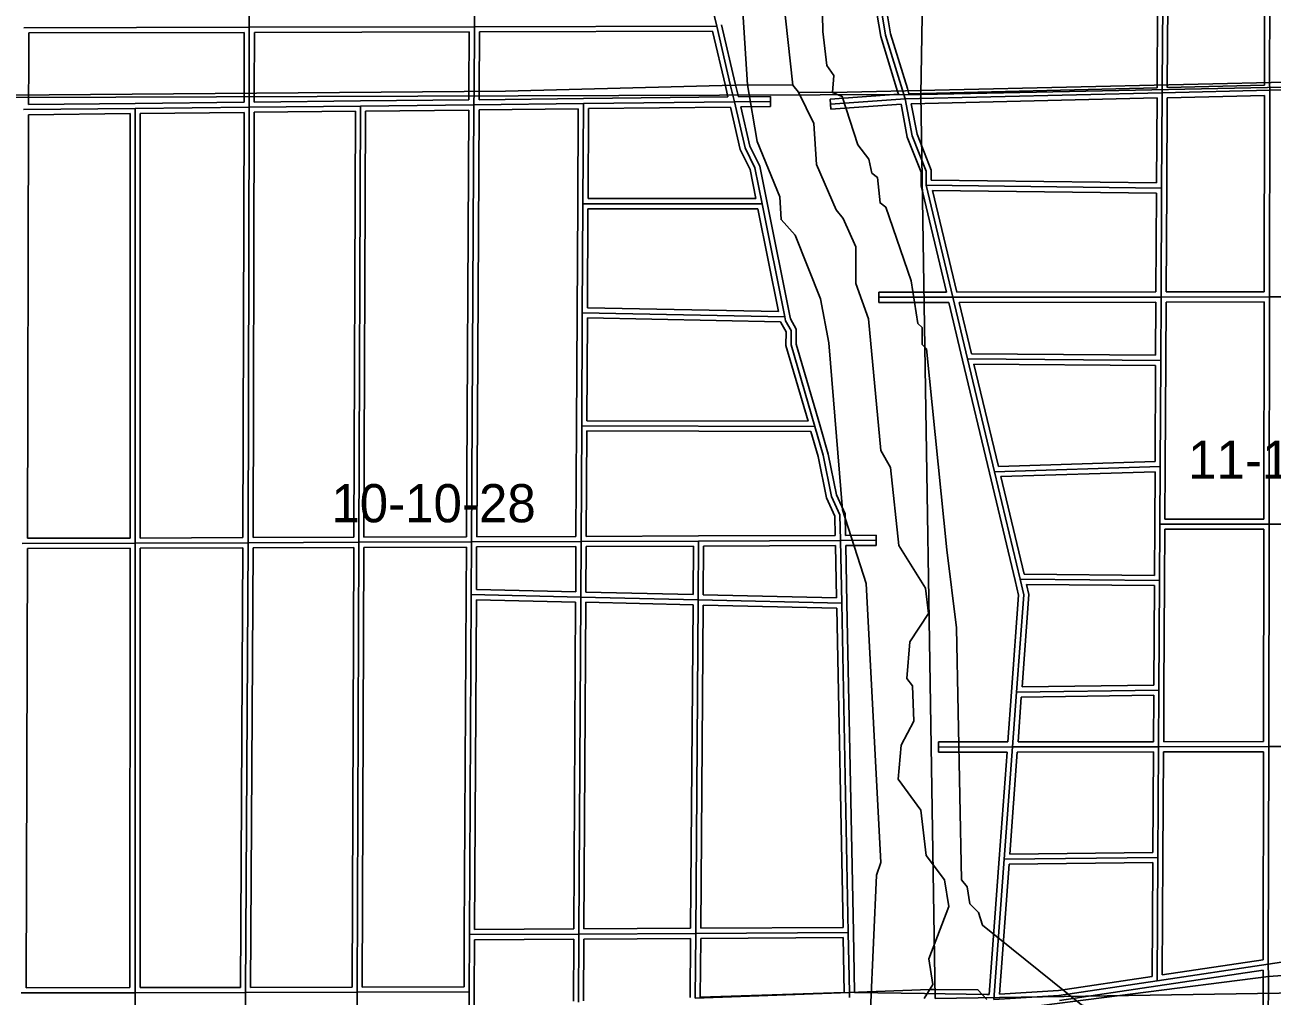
# Model space of a CAD drawing. Extents: x 418523 to 616617, y 1878279 to 2196743.
# Drawn here: x 505579 to 512924, y 1928489 to 1934208 of the extents above; entities that cross this region are included whole.
import ezdxf

# ---------------------------------------------------------------- set-up
doc = ezdxf.new("R2010")
doc.units = 0
for name, color, linetype in [('Level 1', 7, 'Continuous'), ('Level 2', 7, 'Continuous'), ('Level 31', 7, 'Continuous'), ('Level 32', 7, 'Continuous'), ('Level 5', 7, 'Continuous'), ('Level 7', 7, 'Continuous')]:
    doc.layers.add(name, color=color, linetype=linetype)

msp = doc.modelspace()

# ---------------------------------------------------------------- linework, layer by layer
at = {"layer": 'Level 1'}
for p, q in [((510939.835, 1939212.011), (510855.55, 1933798.987)), ((510855.55, 1933798.987), (516178.375, 1933906.316)), ((505521.617, 1933779.822), (510855.55, 1933798.987)), ((510855.55, 1933798.987), (510940.083, 1928474.48)), ((516240.655, 1928555.995), (510940.083, 1928474.48))]:
    msp.add_line(p, q, dxfattribs=at)
at = {"layer": 'Level 31'}
for p, q in [((506901.485, 1934859.173), (506900.067, 1934194.053)), ((508229.261, 1934859.278), (508225.655, 1934197.077)), ((509652.895, 1934200.835), (509498.59, 1934859.664)), ((512910.38, 1934429.871), (512909.801, 1933871.301)), ((512279.751, 1934325.775), (512276.974, 1933857.399)), ((505571.62, 1934191.089), (506900.067, 1934194.053)), ((506900.067, 1934194.053), (506899.148, 1933809.31)), ((506900.067, 1934194.053), (508225.655, 1934197.077)), ((508225.655, 1934197.077), (508223.83, 1933820.701)), ((508225.655, 1934197.077), (509652.895, 1934200.835)), ((509733.165, 1933856.136), (509652.895, 1934200.835)), ((509757.221, 1933754.217), (509733.165, 1933856.136)), ((512276.974, 1933857.399), (512276.782, 1933808.306)), ((512909.801, 1933871.301), (512909.934, 1933823.661)), ((506899.148, 1933809.31), (506899.115, 1933722.76)), ((508223.83, 1933820.701), (508223.495, 1933737.062)), ((510763.317, 1933772.057), (510747.321, 1933824.122)), ((510763.317, 1933772.057), (512276.782, 1933808.306)), ((512276.782, 1933808.306), (512273.642, 1933246.836)), ((512276.782, 1933808.306), (512909.934, 1933823.661)), ((512909.934, 1933823.661), (512908.071, 1932606.155)), ((512909.934, 1933823.661), (513574.537, 1933839.997)), ((505570.289, 1933708.887), (506227.872, 1933715.663)), ((506227.872, 1933715.663), (506227.648, 1931155.896)), ((506227.872, 1933715.663), (506899.115, 1933722.76)), ((506899.115, 1933722.76), (506892.566, 1931158.291)), ((506899.115, 1933722.76), (507555.111, 1933729.931)), ((507555.111, 1933729.931), (507545.411, 1931160.747)), ((507555.111, 1933729.931), (508223.495, 1933737.062)), ((508223.495, 1933737.062), (508209.375, 1931163.17)), ((508223.495, 1933737.062), (508868.055, 1933744.301)), ((508868.055, 1933744.301), (508865.069, 1933154.829)), ((508868.055, 1933744.301), (509757.221, 1933754.217)), ((509757.221, 1933754.217), (509969.745, 1933756.647)), ((510763.317, 1933772.057), (510323.875, 1933741.426)), ((510886.474, 1933263.183), (512273.642, 1933246.836)), ((511043.668, 1932603.986), (510886.474, 1933263.183)), ((512273.642, 1933246.836), (512270.19, 1932605.364)), ((508865.069, 1933154.829), (508861.555, 1932512.628)), ((508865.069, 1933154.829), (509920.667, 1933154.992)), ((510053.675, 1932488.978), (509920.667, 1933154.992)), ((511043.668, 1932603.986), (510607.509, 1932603.886)), ((512270.19, 1932605.364), (511043.668, 1932603.986)), ((511130.237, 1932241.082), (511043.668, 1932603.986)), ((512270.19, 1932605.364), (512268.1, 1932231.899)), ((512908.071, 1932606.155), (512270.19, 1932605.364)), ((512908.071, 1932606.155), (512906.058, 1931267.551)), ((513575.179, 1932607.206), (512908.071, 1932606.155)), ((508861.555, 1932512.628), (508857.949, 1931847.155)), ((508861.555, 1932512.628), (510053.675, 1932488.978)), ((511130.237, 1932241.082), (512268.1, 1932231.899)), ((511288.69, 1931576.427), (511130.237, 1932241.082)), ((512268.1, 1932231.899), (512264.714, 1931607.155)), ((508857.949, 1931847.155), (508853.96, 1931165.681)), ((508857.949, 1931847.155), (510230.927, 1931843.517)), ((511288.69, 1931576.427), (512264.714, 1931607.155)), ((511439.648, 1930943.076), (511288.69, 1931576.427)), ((512264.714, 1931607.155), (512263.075, 1931267.508)), ((512263.075, 1931267.508), (512261.147, 1930935.863)), ((512263.075, 1931267.508), (512906.058, 1931267.551)), ((512906.058, 1931267.551), (512904.156, 1929957.678)), ((512906.058, 1931267.551), (513576.045, 1931267.866)), ((505563.369, 1931154.238), (506227.648, 1931155.896)), ((506227.648, 1931155.896), (506227.388, 1928508.127)), ((506227.648, 1931155.896), (506892.566, 1931158.291)), ((506892.566, 1931158.291), (506877.735, 1928509.491)), ((506892.566, 1931158.291), (507545.411, 1931160.747)), ((507545.411, 1931160.747), (507535.706, 1928510.836)), ((507545.411, 1931160.747), (508209.375, 1931163.17)), ((508209.375, 1931163.17), (508207.817, 1930853.343)), ((508209.375, 1931163.17), (508853.96, 1931165.681)), ((508853.96, 1931165.681), (508852.336, 1930838.036)), ((508853.96, 1931165.681), (509546.197, 1931168.016)), ((509546.197, 1931168.016), (509543.87, 1930821.826)), ((509546.197, 1931168.016), (510382.348, 1931171.612)), ((510382.348, 1931171.612), (510592.021, 1931172.603)), ((510389.785, 1930802.111), (510382.348, 1931171.612)), ((511439.648, 1930943.076), (512261.147, 1930935.863)), ((512261.147, 1930935.863), (512257.365, 1930290.756)), ((508207.817, 1930853.343), (508196.62, 1928850.378)), ((508207.817, 1930853.343), (508852.336, 1930838.036)), ((508852.336, 1930838.036), (508841.25, 1928853.982)), ((508852.336, 1930838.036), (509543.87, 1930821.826)), ((509543.87, 1930821.826), (509529.406, 1928857.788)), ((509543.87, 1930821.826), (510389.785, 1930802.111)), ((510427.885, 1928863.321), (510389.785, 1930802.111)), ((511395.433, 1929955.565), (511419.255, 1930278.761)), ((511419.255, 1930278.761), (512257.365, 1930290.756)), ((512257.365, 1930290.756), (512255.427, 1929956.566)), ((512904.156, 1929957.678), (512255.427, 1929956.566)), ((512904.156, 1929957.678), (512902.05, 1928676.535)), ((513576.712, 1929958.71), (512904.156, 1929957.678)), ((511395.433, 1929955.565), (510959.559, 1929955.096)), ((511346.778, 1929294.633), (511395.433, 1929955.565)), ((512255.427, 1929956.566), (511395.433, 1929955.565)), ((512255.427, 1929956.566), (512251.62, 1929305.276)), ((511346.778, 1929294.633), (512251.62, 1929305.276)), ((512251.62, 1929305.276), (512247.199, 1928577.986)), ((511285.399, 1928467.926), (511346.778, 1929294.633)), ((508841.25, 1928853.982), (509529.406, 1928857.788)), ((509529.406, 1928857.788), (509526.306, 1928477.054)), ((509529.406, 1928857.788), (510427.885, 1928863.321)), ((510434.752, 1928509.821), (510427.885, 1928863.321)), ((508196.62, 1928850.378), (508194.951, 1928512.914)), ((508196.62, 1928850.378), (508841.25, 1928853.982)), ((508841.25, 1928853.982), (508838.696, 1928452.518)), ((512247.199, 1928577.986), (512902.05, 1928676.535)), ((512902.05, 1928676.535), (512902.086, 1928604.167)), ((511668.96, 1928491.515), (512247.199, 1928577.986)), ((512902.086, 1928604.167), (512901.062, 1927929.958)), ((505556.391, 1928506.859), (506227.388, 1928508.127)), ((506227.388, 1928508.127), (506877.735, 1928509.491)), ((506227.388, 1928508.127), (506227.392, 1928430.669)), ((506877.735, 1928509.491), (506877.416, 1928430.579)), ((506877.735, 1928509.491), (507535.706, 1928510.836)), ((507535.706, 1928510.836), (507535.385, 1928430.833)), ((507535.706, 1928510.836), (508194.951, 1928512.914)), ((508194.951, 1928512.914), (508194.305, 1928430.731)), ((510435.269, 1928479.636), (510434.752, 1928509.821)), ((511285.399, 1928467.926), (511668.96, 1928491.515))]:
    msp.add_line(p, q, dxfattribs=at)
for points in [[(510747.321, 1933824.122), (510648.215, 1934147.438), (510615.295, 1934338.123)], [(509920.667, 1933154.992), (509878.303, 1933366.808), (509820.317, 1933483.771), (509757.221, 1933754.217)], [(510886.474, 1933263.183), (510886.8, 1933346.458), (510804.395, 1933555.156), (510763.317, 1933772.057)], [(510230.927, 1931843.517), (510091.144, 1932324.094), (510091.473, 1932407.37), (510058.349, 1932465.686), (510053.675, 1932488.978)], [(510382.348, 1931171.612), (510379.131, 1931322.541), (510329.366, 1931431.108), (510280.447, 1931673.131), (510230.927, 1931843.517)], [(511419.255, 1930278.761), (511461.21, 1930851.714), (511439.648, 1930943.076)], [(512902.05, 1928676.535), (513187.194, 1928719.431), (513576.794, 1928744.834)]]:
    msp.add_lwpolyline(points, dxfattribs=at)
at = {"layer": 'Level 32'}
for p, q in [((512880.38, 1934429.901), (512879.801, 1933871.331)), ((512249.575, 1934295.997), (512246.975, 1933857.576)), ((512309.752, 1934325.596), (512306.975, 1933857.22)), ((505601.534, 1934161.154), (505600.835, 1933920.445)), ((505601.534, 1934161.155), (506869.995, 1934163.985)), ((506869.995, 1934163.985), (506869.149, 1933809.381)), ((506929.996, 1934164.12), (506929.149, 1933809.238)), ((506929.997, 1934164.121), (508195.51, 1934167.007)), ((508195.51, 1934167.007), (508193.83, 1933820.846)), ((508255.512, 1934167.154), (508253.831, 1933820.555)), ((508255.512, 1934167.155), (509629.094, 1934170.771)), ((509703.946, 1933849.331), (509629.094, 1934170.771)), ((509762.385, 1933862.94), (509682.115, 1934207.639)), ((505600.835, 1933920.41), (505600.336, 1933798.224)), ((509780.902, 1933784.49), (509762.365, 1933863.027)), ((512246.975, 1933857.516), (512246.897, 1933837.6)), ((512306.975, 1933857.281), (512306.904, 1933839.046)), ((512306.904, 1933839.046), (512879.853, 1933852.941)), ((512879.801, 1933871.217), (512879.853, 1933852.941)), ((505600.336, 1933798.331), (505600.306, 1933739.198)), ((506869.149, 1933809.321), (506869.128, 1933752.444)), ((506929.149, 1933809.298), (506929.128, 1933753.089)), ((508193.83, 1933820.821), (508193.615, 1933766.744)), ((508253.831, 1933820.581), (508253.619, 1933767.402)), ((508867.721, 1933774.299), (509719.415, 1933783.797)), ((509719.415, 1933783.797), (509703.968, 1933849.243)), ((509780.901, 1933784.49), (509969.402, 1933786.646)), ((509969.402, 1933786.646), (509970.089, 1933726.648)), ((510723.546, 1933799.357), (510321.789, 1933771.354)), ((510723.546, 1933799.357), (510718.644, 1933815.311)), ((510785.32, 1933802.593), (510775.999, 1933832.933)), ((510785.32, 1933802.592), (512246.897, 1933837.6)), ((510799.372, 1933742.911), (512246.61, 1933777.574)), ((512246.61, 1933777.573), (512243.812, 1933277.189)), ((512306.62, 1933779.021), (512303.643, 1933246.668)), ((512306.621, 1933779.02), (512879.887, 1933792.921)), ((512879.887, 1933792.921), (512878.118, 1932636.117)), ((505600.306, 1933739.198), (506227.564, 1933745.662)), ((506227.555, 1933745.661), (506869.127, 1933752.444)), ((506929.128, 1933753.089), (507554.783, 1933759.928)), ((507554.791, 1933759.928), (508193.615, 1933766.744)), ((507585, 1933700.246), (508193.329, 1933706.738)), ((508193.329, 1933706.737), (508179.54, 1931193.061)), ((508253.335, 1933707.394), (508239.543, 1931193.288)), ((508253.334, 1933707.395), (508837.9, 1933713.959)), ((508253.619, 1933767.401), (508867.719, 1933774.299)), ((508837.9, 1933713.959), (508835.069, 1933154.981)), ((508897.906, 1933714.63), (508895.222, 1933184.833)), ((508897.906, 1933714.631), (509733.477, 1933723.949)), ((509794.928, 1933724.645), (509970.089, 1933726.648)), ((510325.96, 1933711.498), (510321.789, 1933771.354)), ((510738.803, 1933740.274), (510325.96, 1933711.498)), ((505600.21, 1933679.192), (505593.451, 1931184.312)), ((505600.21, 1933679.192), (506197.87, 1933685.351)), ((506197.87, 1933685.351), (506197.65, 1931185.821)), ((506257.871, 1933685.977), (506257.651, 1931186.005)), ((506257.872, 1933685.978), (506869.039, 1933692.439)), ((506869.039, 1933692.439), (506862.643, 1931188.183)), ((506929.041, 1933693.084), (506922.645, 1931188.405)), ((506929.042, 1933693.084), (507524.997, 1933699.598)), ((507524.997, 1933699.597), (507515.525, 1931190.635)), ((507585, 1933700.246), (507575.526, 1931190.857)), ((510916.591, 1933292.83), (512243.812, 1933277.19)), ((511005.675, 1932633.977), (510856.46, 1933259.713)), ((510924.578, 1933232.73), (512243.482, 1933217.188)), ((511067.35, 1932634.011), (510924.578, 1933232.73)), ((512243.482, 1933217.188), (512240.352, 1932635.33)), ((512303.643, 1933246.674), (512300.354, 1932635.401)), ((508835.069, 1933154.992), (508831.555, 1932512.791)), ((508894.907, 1933124.832), (508891.717, 1932542.036)), ((508894.907, 1933124.833), (509896.067, 1933124.987)), ((508895.222, 1933184.833), (509884.075, 1933184.986)), ((510016.945, 1932519.712), (509896.066, 1933124.987)), ((510083.096, 1932494.853), (509950.088, 1933160.867)), ((511005.675, 1932633.976), (510607.502, 1932633.886)), ((510607.515, 1932573.885), (510607.502, 1932633.886)), ((512240.352, 1932635.33), (511067.35, 1932634.011)), ((512878.117, 1932636.116), (512300.354, 1932635.401)), ((508891.717, 1932542.035), (510016.945, 1932519.712)), ((511019.984, 1932573.978), (510607.515, 1932573.885)), ((511101.055, 1932234.121), (511019.985, 1932573.978)), ((512240.022, 1932575.328), (511081.656, 1932574.026)), ((511153.969, 1932270.891), (511081.657, 1932574.026)), ((512240.022, 1932575.328), (512238.27, 1932262.141)), ((512300.025, 1932575.398), (512298.101, 1932231.731)), ((512878.026, 1932576.116), (512300.025, 1932575.399)), ((512878.027, 1932576.115), (512876.104, 1931297.55)), ((508831.555, 1932512.791), (508827.949, 1931847.317)), ((508891.391, 1932482.029), (508888.113, 1931877.076)), ((508891.391, 1932482.03), (510029, 1932459.461)), ((511259.509, 1931569.47), (511101.055, 1932234.125)), ((511153.969, 1932270.891), (512238.27, 1932262.141)), ((511168.305, 1932210.773), (512237.94, 1932202.141)), ((511312.2, 1931607.181), (511168.305, 1932210.772)), ((512237.939, 1932202.14), (512234.871, 1931636.23)), ((512298.101, 1932231.736), (512294.715, 1931606.991)), ((508888.112, 1931877.075), (510190.926, 1931873.623)), ((508827.949, 1931847.331), (508824.135, 1931195.566)), ((508887.775, 1931817.074), (508884.139, 1931195.784)), ((508887.775, 1931817.075), (510208.388, 1931813.576)), ((511312.2, 1931607.182), (512234.871, 1931636.23)), ((511326.404, 1931547.598), (512234.565, 1931576.188)), ((512234.565, 1931576.189), (512233.075, 1931267.653)), ((512294.715, 1931607.009), (512293.221, 1931297.511)), ((511410.465, 1930936.12), (511259.508, 1931569.471)), ((511463.389, 1930972.869), (511326.404, 1931547.598)), ((512293.221, 1931297.51), (512876.104, 1931297.55)), ((512233.075, 1931267.682), (512231.322, 1930966.126)), ((512292.902, 1931237.509), (512291.148, 1930935.688)), ((512292.902, 1931237.509), (512876.015, 1931237.549)), ((512876.015, 1931237.548), (512874.2, 1929987.626)), ((505593.451, 1931184.312), (506197.65, 1931185.821)), ((506257.652, 1931186.004), (506862.642, 1931188.183)), ((506922.645, 1931188.404), (507515.525, 1931190.635)), ((507575.304, 1931130.854), (508179.224, 1931133.058)), ((507575.527, 1931190.856), (508179.54, 1931193.061)), ((508179.224, 1931133.058), (508177.817, 1930853.493)), ((508239.226, 1931133.285), (508237.966, 1930882.636)), ((508239.226, 1931133.285), (508823.81, 1931135.562)), ((508239.543, 1931193.288), (508824.135, 1931195.566)), ((508823.811, 1931135.563), (508822.489, 1930868.754)), ((508883.815, 1931135.781), (508882.484, 1930867.336)), ((508883.815, 1931135.781), (509515.994, 1931137.912)), ((508884.139, 1931195.784), (509546.096, 1931198.016)), ((509515.994, 1931137.912), (509514.077, 1930852.533)), ((509546.068, 1931198.016), (510351.705, 1931201.481)), ((509575.999, 1931138.142), (509574.07, 1930851.131)), ((509575.998, 1931138.142), (510352.949, 1931141.485)), ((510359.162, 1930832.833), (510352.949, 1931141.485)), ((510411.714, 1931201.751), (510591.88, 1931202.602)), ((510412.956, 1931141.756), (510592.164, 1931142.602)), ((510419.78, 1930802.714), (510412.956, 1931141.755)), ((510591.88, 1931202.602), (510592.164, 1931142.602)), ((505593.29, 1931124.311), (505586.471, 1928536.916)), ((505593.291, 1931124.311), (506197.645, 1931125.821)), ((506197.645, 1931125.821), (506197.392, 1928538.071)), ((506257.645, 1931126.003), (506257.392, 1928538.191)), ((506257.646, 1931126.003), (506862.398, 1931128.181)), ((506862.397, 1931128.181), (506847.902, 1928539.429)), ((506922.4, 1931128.401), (506907.905, 1928539.552)), ((506922.4, 1931128.401), (507515.3, 1931130.633)), ((507515.301, 1931130.631), (507505.816, 1928540.774)), ((507575.304, 1931130.854), (507565.818, 1928540.931)), ((511463.389, 1930972.869), (512231.322, 1930966.126)), ((511477.632, 1930912.74), (512230.973, 1930906.126)), ((512291.148, 1930935.686), (512287.365, 1930290.579)), ((508177.817, 1930853.51), (508166.62, 1928850.546)), ((508237.966, 1930882.635), (508822.489, 1930868.753)), ((508882.485, 1930867.337), (509514.077, 1930852.533)), ((509574.07, 1930851.131), (510359.162, 1930832.833)), ((512230.972, 1930906.126), (512227.537, 1930320.331)), ((508237.647, 1930822.625), (508226.791, 1928880.548)), ((508237.647, 1930822.625), (508822.172, 1930808.742)), ((508822.172, 1930808.742), (508811.416, 1928883.816)), ((508882.167, 1930807.327), (508871.421, 1928884.15)), ((508882.167, 1930807.326), (509513.654, 1930792.524)), ((509513.654, 1930792.524), (509499.625, 1928887.623)), ((509573.647, 1930791.122), (509559.631, 1928887.975)), ((509573.647, 1930791.122), (510360.356, 1930772.786)), ((510397.294, 1928893.132), (510360.355, 1930772.787)), ((510457.881, 1928863.909), (510419.781, 1930802.7)), ((511367.561, 1929985.535), (511389.336, 1930280.965)), ((511447.155, 1930249.155), (512227.188, 1930260.319)), ((511451.568, 1930309.226), (512227.537, 1930320.331)), ((512227.188, 1930260.32), (512225.6, 1929986.531)), ((512287.365, 1930290.581), (512285.603, 1929986.617)), ((511427.73, 1929985.603), (511447.156, 1930249.156)), ((511367.561, 1929985.535), (510959.526, 1929985.096)), ((510959.592, 1929925.096), (510959.526, 1929985.096)), ((512225.6, 1929986.53), (511427.73, 1929985.602)), ((512874.2, 1929987.626), (512285.603, 1929986.616)), ((511363.141, 1929925.529), (510959.592, 1929925.096)), ((511316.859, 1929296.836), (511363.141, 1929925.529)), ((511379.097, 1929325.015), (511423.309, 1929925.596)), ((512225.251, 1929926.529), (511423.31, 1929925.596)), ((512225.251, 1929926.529), (512221.793, 1929334.928)), ((512285.254, 1929926.614), (512281.621, 1929305.101)), ((512874.107, 1929927.625), (512285.254, 1929926.615)), ((512874.107, 1929927.624), (512872.092, 1928702.364)), ((511257.569, 1928498.276), (511316.86, 1929296.855)), ((511379.097, 1929325.015), (512221.793, 1929334.928)), ((512281.621, 1929305.094), (512277.413, 1928612.871)), ((511317.862, 1928499.979), (511374.66, 1929264.957)), ((511374.659, 1929264.958), (512221.435, 1929274.918)), ((512221.435, 1929274.918), (512217.355, 1928603.856)), ((508226.791, 1928880.548), (508811.416, 1928883.816)), ((508871.421, 1928884.149), (509499.625, 1928887.623)), ((509559.631, 1928887.975), (510397.294, 1928893.132)), ((510464.748, 1928510.403), (510457.881, 1928863.902)), ((508166.62, 1928850.526), (508165.099, 1928542.821)), ((508226.475, 1928820.543), (508224.952, 1928512.766)), ((508226.474, 1928820.543), (508811.057, 1928823.811)), ((508811.057, 1928823.811), (508808.737, 1928459.083)), ((508871.063, 1928824.145), (508868.752, 1928460.918)), ((508871.062, 1928824.145), (509499.16, 1928827.618)), ((509499.16, 1928827.618), (509496.332, 1928480.324)), ((509559.165, 1928827.969), (509556.35, 1928482.191)), ((509559.166, 1928827.969), (510398.466, 1928833.136)), ((510404.757, 1928509.238), (510398.466, 1928833.136)), ((512251.664, 1928548.319), (512872.067, 1928641.683)), ((512277.413, 1928612.871), (512872.092, 1928702.364)), ((512872.068, 1928641.683), (512872.086, 1928604.151)), ((511665.815, 1928521.377), (512217.356, 1928603.857)), ((512872.086, 1928604.151), (512871.108, 1927959.912)), ((505586.472, 1928536.915), (506197.391, 1928538.071)), ((506257.392, 1928538.191), (506847.902, 1928539.428)), ((506907.905, 1928539.552), (507505.816, 1928540.774)), ((507565.818, 1928540.93), (508165.098, 1928542.819)), ((508224.951, 1928512.678), (508224.305, 1928430.611)), ((509556.35, 1928482.191), (510404.767, 1928508.698)), ((510404.767, 1928508.697), (510404.756, 1928509.307)), ((510464.768, 1928509.231), (510464.749, 1928510.334)), ((510876.315, 1928503.533), (510464.768, 1928509.231)), ((511243.561, 1928498.452), (510876.315, 1928503.533)), ((511257.57, 1928498.276), (511243.522, 1928498.453)), ((511317.862, 1928499.979), (511665.815, 1928521.377)), ((511672.105, 1928461.65), (512251.636, 1928548.315))]:
    msp.add_line(p, q, dxfattribs=at)
for points in [[(510718.638, 1933815.33), (510618.975, 1934140.463), (510585.732, 1934333.02)], [(510776.004, 1933832.915), (510677.455, 1934154.414), (510650.965, 1934307.856)], [(509884.074, 1933184.987), (509849.663, 1933357.036), (509791.892, 1933473.564), (509733.477, 1933723.949)], [(509950.085, 1933160.876), (509906.944, 1933376.58), (509848.743, 1933493.977), (509794.928, 1933724.644)], [(510856.46, 1933259.712), (510856.777, 1933340.806), (510775.447, 1933546.782), (510738.803, 1933740.273)], [(510916.591, 1933292.831), (510916.823, 1933352.109), (510833.343, 1933563.531), (510799.372, 1933742.911)], [(510190.927, 1931873.623), (510061.126, 1932319.877), (510061.44, 1932399.5), (510029.882, 1932455.06), (510029, 1932459.461)], [(510259.734, 1931851.896), (510121.16, 1932328.311), (510121.505, 1932415.241), (510086.815, 1932476.312), (510083.09, 1932494.88)], [(510351.705, 1931201.481), (510349.27, 1931315.69), (510300.649, 1931421.762), (510251.289, 1931665.961), (510208.388, 1931813.576)], [(510411.714, 1931201.751), (510408.992, 1931329.394), (510358.085, 1931440.453), (510309.605, 1931680.301), (510259.735, 1931851.89)], [(511389.335, 1930280.951), (511430.953, 1930849.309), (511410.449, 1930936.185)], [(511451.568, 1930309.226), (511491.467, 1930854.12), (511477.632, 1930912.74)]]:
    msp.add_lwpolyline(points, dxfattribs=at)
at = {"layer": 'Level 5'}
for p, q in [((510101.193, 1933853.131), (510004.035, 1934753.75)), ((510101.193, 1933853.131), (509834.437, 1933853.987)), ((510134.414, 1933811.32), (510101.193, 1933853.131)), ((510334.479, 1933810.702), (515178.26, 1933920.188)), ((510334.479, 1933810.702), (510134.414, 1933811.32)), ((509526.306, 1928477.054), (510434.752, 1928509.821)), ((510434.752, 1928509.821), (510907.245, 1928526.869))]:
    msp.add_line(p, q, dxfattribs=at)
for points in [[(497411.956, 1933728.456), (508408.787, 1933816.877), (509834.437, 1933853.987)], [(510875.916, 1928473.636), (510926.196, 1928556.838), (510901.643, 1928706.991), (511019.36, 1929015.04), (510994.846, 1929173.533), (510886.931, 1929315.575), (510854.436, 1929582.471), (510721.64, 1929766.293), (510738.966, 1929966.298), (510814.445, 1930107.792), (510806.761, 1930316.227), (510773.58, 1930358.008), (510790.936, 1930574.693), (510899.836, 1930741.088), (510883.653, 1930891.181), (510726.075, 1931141.796), (510677.525, 1931600.456), (510619.463, 1931700.657), (510546.957, 1932476.194), (510472.581, 1932684.838), (510473.268, 1932901.583), (510398.793, 1933068.536), (510357.271, 1933118.686), (510241.414, 1933385.841), (510225.52, 1933627.626), (510134.414, 1933811.32)], [(512902.086, 1928604.167), (513850.695, 1928673.229), (514602.887, 1928723.43), (514988.654, 1928743.771)], [(511286.167, 1928420.648), (511305.779, 1928398.751), (512902.086, 1928604.167)], [(510907.245, 1928526.869), (510935.841, 1928527.847), (511191.903, 1928525.75), (511243.145, 1928468.455)]]:
    msp.add_lwpolyline(points, dxfattribs=at)
at = {"layer": 'Level 7'}
for points in [[(509834.437, 1933853.987), (509802.657, 1934345.928), (509828.025, 1934462.571), (509812.489, 1934812.729), (509746.683, 1935088.055), (509680.25, 1935171.616), (509647.884, 1935471.852), (509622.913, 1935488.592), (509598.589, 1935697.066), (509573.647, 1935722.177), (509516.141, 1935989.132), (509459.54, 1936539.494)], [(510334.479, 1933810.702), (510343.117, 1933910.705), (510301.625, 1933969.186), (510277.27, 1934169.33), (510270.243, 1934577.84), (510338.108, 1934944.439)], [(509834.437, 1933853.987), (509891.714, 1933520.33), (510024.043, 1933194.794), (510031.955, 1933061.371), (510115.029, 1932969.41), (510263.879, 1932593.783), (510313.075, 1932335.228), (510393.274, 1931351.246), (510533.595, 1930917.328), (510620.036, 1929274.771), (510594.797, 1929199.809), (510558.911, 1928407.99)], [(510334.479, 1933810.702), (510392.74, 1933785.492), (510483.527, 1933501.767), (510549.95, 1933418.176), (510566.362, 1933334.774), (510599.613, 1933309.664), (510615.826, 1933159.551), (510649.077, 1933134.441), (510797.758, 1932700.462), (510838.624, 1932450.237), (510863.575, 1932425.127), (510863.246, 1932325.095), (510888.157, 1932300.025), (511009.411, 1931115.868), (511066.301, 1930657.169), (511094.878, 1929173.205), (511128.1, 1929131.424), (511144.442, 1929031.321), (511194.294, 1928981.141), (511219.075, 1928906.05), (511801.116, 1928437.346), (512558.718, 1928118.109), (512725.113, 1928017.559), (513073.869, 1927582.923)]]:
    msp.add_lwpolyline(points, dxfattribs=at)

# ---------------------------------------------------------------- texts
at = {"layer": 'Level 2'}
for s, p in [('11-10-28', (512429.527, 1931534.953)), ('10-10-28', (507383.032, 1931278.583))]:
    msp.add_text(s, height=225, dxfattribs=at).set_placement(p)

doc.saveas('drawing.dxf')
